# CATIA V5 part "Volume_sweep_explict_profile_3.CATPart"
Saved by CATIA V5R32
Part number: Part1
Bounding box of the stored display mesh (mm): x -10 to 10, y -11.899 to 23.172, z 0 to 127.486
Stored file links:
  D:\PROJECTS\Project 2022\CATIA V5 6R 2022\Resources\Part Files\c17_catia_v6_6r2022_prt\Volume_sweep_explict_profile_3.CATPart
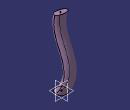
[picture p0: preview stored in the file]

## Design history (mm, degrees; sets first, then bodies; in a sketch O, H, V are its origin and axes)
Set1
  Sketch1 on xy-plane, origin (0, 0, 0), H (1, 0, 0), V (0, 1, 0)
    circle A1 centre (0, 0) radius 10
    radius A1 = 10
  Sketch2 on yz-plane, origin (0, 0, 0), H (0, 1, 0), V (0, 0, 1)
    spline S1 through (0, 0) (11.9407, 56.843) (-3.4307, 102.6672) (-1.4005, 123.8391)
    point P1 (0, 0)
    coincidence: P1 O
  Sweep1: type Unspec, Profile Sketch1, Guide Sketch2, AngleRef 0, PullingDir zx-plane
Body1 (main body)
